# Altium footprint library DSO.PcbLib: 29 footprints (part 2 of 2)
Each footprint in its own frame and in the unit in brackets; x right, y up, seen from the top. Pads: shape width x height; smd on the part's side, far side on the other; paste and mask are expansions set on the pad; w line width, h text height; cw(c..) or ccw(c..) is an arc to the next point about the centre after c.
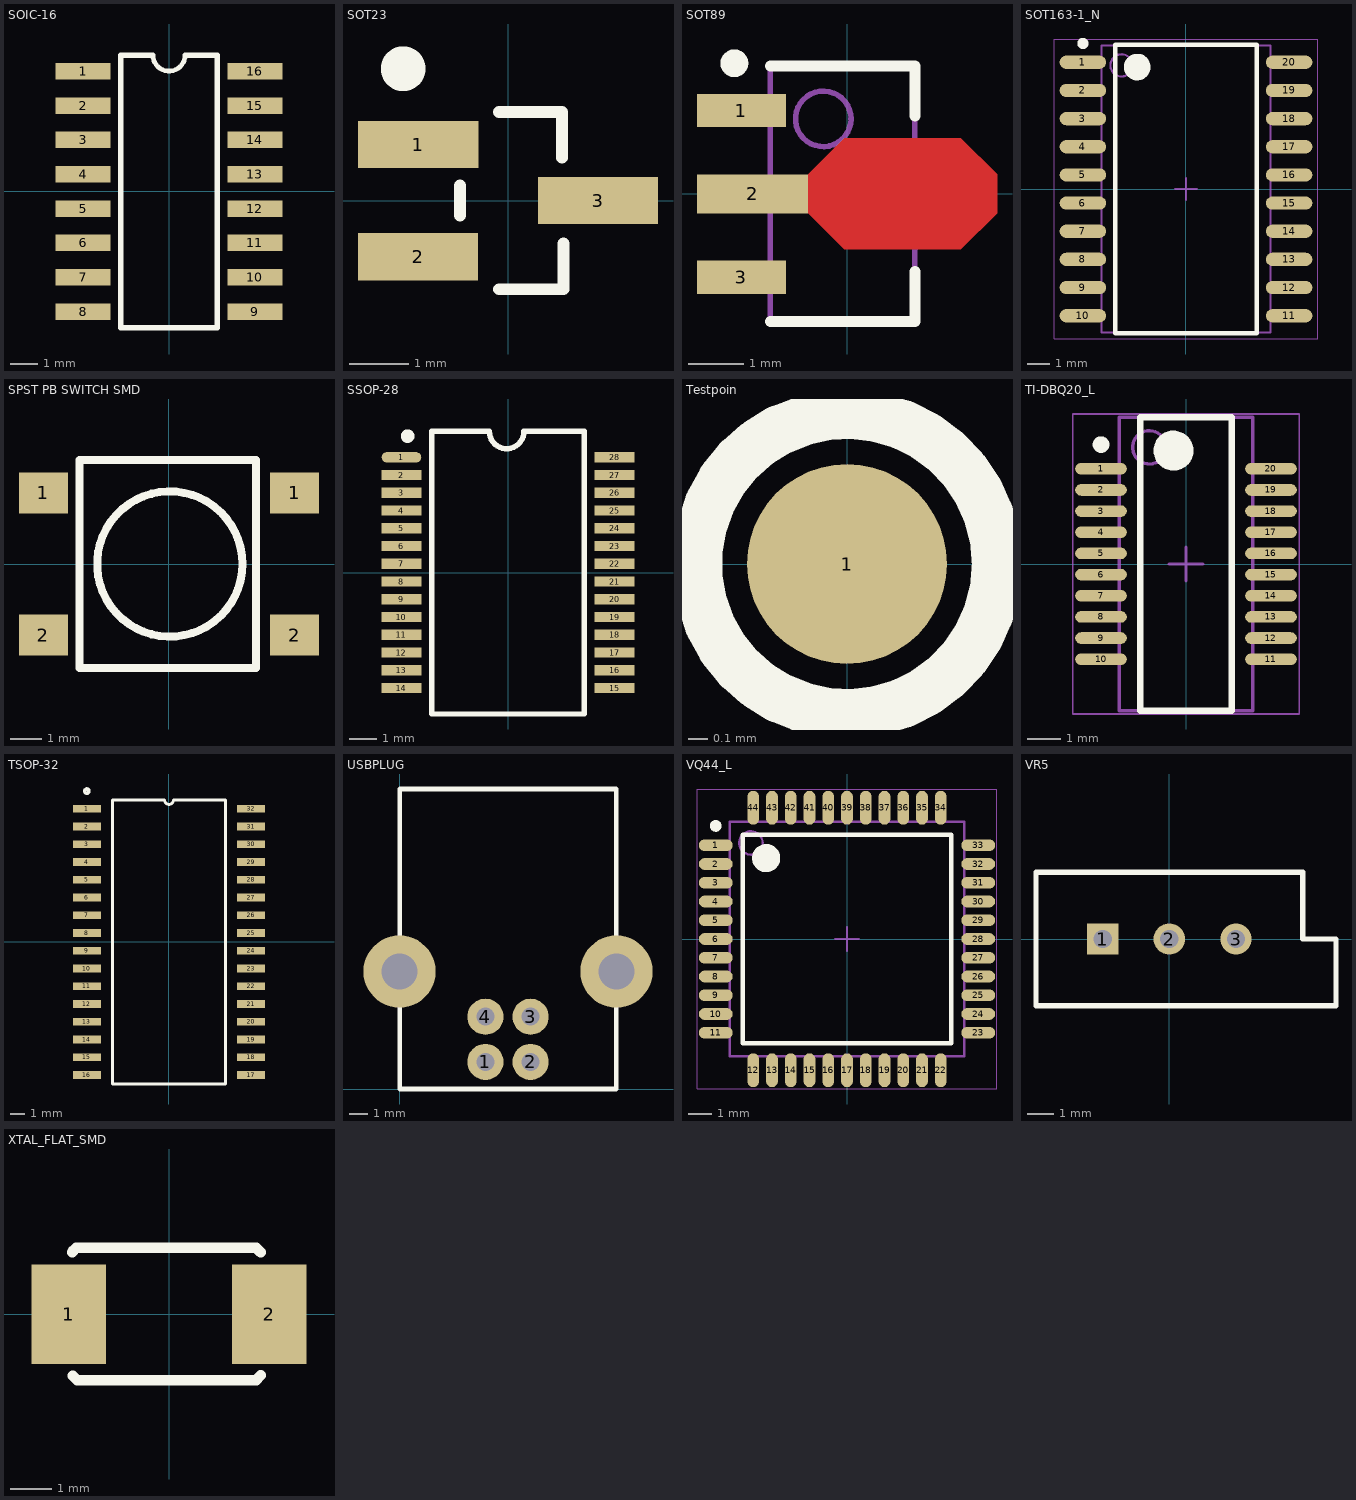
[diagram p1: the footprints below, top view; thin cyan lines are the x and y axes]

## SOIC-16 [mil] "SOIC-16 Footprint"
height 68.9
pads (16):
  rect 80x24 smd: 1(-125,175) 2(-125,125) 3(-125,75) 4(-125,25) 5(-125,-25) 6(-125,-75) 7(-125,-125) 8(-125,-175) 9(125,-175) 10(125,-125) 11(125,-75) 12(125,-25) 13(125,25) 14(125,75) 15(125,125) 16(125,175)
Top Overlay:
  lines w7: -23.43,198.43 ccw(c0,198.43) 23.43,198.43
  lines w7.87: -23.43,198.43 -70,198.43 -70,-198.43 70,-198.43 70,198.43 23.43,198.43
3D body "SOIC127P600X175-16M.step": height 68.9, standoff 0, extent -118.11,-196.85 118.11,196.85

## SOT23 [mm] "SOT23, 3-Leads, Body 3.0x2.5mm (max), Pitch 0.95mm, IPC Low Density"
height 1.35
pads (3):
  rect 2.038x0.8 smd: 1(-1.524,0.95)
  rect 2.032x0.8 smd: 2(-1.524,-0.95) 3(1.524,0)
Top Overlay:
  circle w0.508: c-1.776,2.235 r0.125
  lines w0.2: -0.813,-0.254 -0.813,0.254 ; -0.152,-1.5 0.94,-1.5 0.94,-0.725 ; -0.152,1.5 0.914,1.5 0.914,0.725
3D body "User Library-SOT23-2.step": height 1.08, standoff 0, extent -1.32,-1.5 1.32,1.5

## SOT89 [mm] "SOT89, 3-Leads, Body 4.50x2.50mm, Pitch 1.50mm, Lead Span 4.1mm, IPC Low Density"
height 1.6
pads (3):
  rect 1.6x0.6 smd: 1(-1.9,1.5) 3(-1.9,-1.5)
  rect 2x0.7 smd: 2(-1.7,0)
Top Layer:
  region: -0.7,0.35 -0.05,1 2.05,1 2.7,0.35 2.7,-0.35 2.05,-1 -0.05,-1 -0.7,-0.35
Top Overlay:
  circle w0.25: c-2.027,2.35 r0.125
  lines w0.2: -1.378,-2.3 1.222,-2.3 1.222,-1.4 ; -1.378,2.3 1.222,2.3 1.222,1.4
Mechanical 13:
  circle w0.1: c-0.427,1.35 r0.5
  lines w0.1: -1.378,-2.3 -1.378,2.3 1.222,2.3 1.222,-2.3 -1.378,-2.3
Mechanical 15:
  lines w0.1: -0.577,0 0.423,0 ; -0.078,-0.5 -0.078,0.5
3D body "SOT89-150P410X160-3M.step": height 1.6, standoff 0, extent -2.2,-2.3 1.85,2.3

## SOT163-1_N [mm] "SOIC, 20-Leads, Body 12.7x7.5mm, Pitch 1.27mm, IPC Medium Density"
height 2.54
pads (20):
  oval 2.1x0.6 smd: 1(-4.65,5.715) 2(-4.65,4.445) 3(-4.65,3.175) 4(-4.65,1.905) 5(-4.65,0.635) 6(-4.65,-0.635) 7(-4.65,-1.905) 8(-4.65,-3.175) 9(-4.65,-4.445) 10(-4.65,-5.715) 11(4.65,-5.715) 12(4.65,-4.445) 13(4.65,-3.175) 14(4.65,-1.905) 15(4.65,-0.635) 16(4.65,0.635) 17(4.65,1.905) 18(4.65,3.175) 19(4.65,4.445) 20(4.65,5.715)
Top Overlay:
  circle w0.6: c-2.2,5.5 r0.3
  circle w0.25: c-4.65,6.565 r0.125
  lines w0.2: -3.2,-6.5 3.2,-6.5 3.2,6.5 -3.2,6.5 -3.2,-6.5
Mechanical 13:
  circle w0.1: c-2.91,5.575 r0.5
  lines w0.1: -3.81,-6.475 3.81,-6.475 3.81,6.475 -3.81,6.475 -3.81,-6.475
Mechanical 15:
  lines w0.05: -5.95,-6.75 5.95,-6.75 5.95,6.75 -5.95,6.75 -5.95,-6.75
  lines w0.1: -0.5,0 0.5,0 ; 0,-0.5 0,0.5
3D body "SOIC127P1030X265-20M.step": height 2.65, standoff 0, extent -5.15,-6.5 5.15,6.5

## SPST PB SWITCH SMD [mm] "Push Button Switch Surface Mount"
height 3
pads (4):
  rect 1.55x1.3 smd: 1(-3.975,2.25) 1(3.975,2.25) 2(-3.975,-2.25) 2(3.975,-2.25)
Top Overlay:
  circle w0.254: c0.025,0 r2.3
  lines w0.254: -2.832,-3.3 2.756,-3.3 2.756,3.3 -2.832,3.3 -2.832,-3.3
3D body "PTS645SH50SMTR92LFS.stp": height 5, standoff 0, extent -4.5,-3 4.5,3

## SSOP-28 [mm] "Line Driver"
height 2
pads (28):
  oval 1.45x0.38 smd: 1(-3.9,4.225)
  rect 1.45x0.38 smd: 2(-3.9,3.575) 3(-3.9,2.925) 4(-3.9,2.275) 5(-3.9,1.625) 6(-3.9,0.975) 7(-3.9,0.325) 8(-3.9,-0.325) 9(-3.9,-0.975) 10(-3.9,-1.625) 11(-3.9,-2.275) 12(-3.9,-2.925) 13(-3.9,-3.575) 14(-3.9,-4.225) 15(3.9,-4.225) 16(3.9,-3.575) 17(3.9,-2.925) 18(3.9,-2.275) 19(3.9,-1.625) 20(3.9,-0.975) 21(3.9,-0.325) 22(3.9,0.325) 23(3.9,0.975) 24(3.9,1.625) 25(3.9,2.275) 26(3.9,2.925) 27(3.9,3.575) 28(3.9,4.225)
Top Overlay:
  circle w0.25: c-3.675,5 r0.125
  lines w0.2: -2.794,-5.175 -2.794,5.175 -0.685,5.175 ccw(c-0.05,5.175) 0.585,5.175 2.794,5.175 2.794,-5.175 -2.794,-5.175
3D body "TSSOP-28.STEP": height 2, standoff 0, extent -3.9,-5.1 3.9,5.1

## Testpoin [mil] "Testpoint"
pads (1):
  round 40 smd: 1(0,0)
Top Overlay:
  circle w10: c0,0 r30

## TI-DBQ20_L [mm] "SOP, 20-Leads, Body 8.65x3.9mm, Pitch 0.635mm, IPC High Density"
height 1.75
pads (20):
  oval 1.55x0.35 smd: 1(-2.55,2.857) 2(-2.55,2.222) 3(-2.55,1.587) 4(-2.55,0.953) 5(-2.55,0.318) 6(-2.55,-0.318) 7(-2.55,-0.953) 8(-2.55,-1.587) 9(-2.55,-2.222) 10(-2.55,-2.857) 11(2.55,-2.857) 12(2.55,-2.222) 13(2.55,-1.587) 14(2.55,-0.953) 15(2.55,-0.318) 16(2.55,0.318) 17(2.55,0.953) 18(2.55,1.587) 19(2.55,2.222) 20(2.55,2.857)
Top Overlay:
  circle w0.25: c-2.55,3.582 r0.125
  circle w0.6: c-0.375,3.4 r0.3
  lines w0.2: -1.375,-4.4 -1.375,4.4 1.375,4.4 1.375,-4.4 -1.375,-4.4
Mechanical 13:
  circle w0.1: c-1.1,3.5 r0.5
  lines w0.1: -2,-4.4 -2,4.4 2,4.4 2,-4.4 -2,-4.4
Mechanical 15:
  lines w0.05: -3.4,-4.5 -3.4,4.5 3.4,4.5 3.4,-4.5 -3.4,-4.5
  lines w0.1: -0.5,0 0.5,0 ; 0,-0.5 0,0.5
3D body "SOP64P600X175-20N.step": height 1.75, standoff 0, extent -3,-4.4 3,4.4

## TSOP-32 [mm]
height 5
pads (32):
  rect 2x0.55 smd: 1(-5.88,9.525) 2(-5.88,8.255) 3(-5.88,6.985) 4(-5.88,5.715) 5(-5.88,4.445) 6(-5.88,3.175) 7(-5.88,1.905) 8(-5.88,0.635) 9(-5.88,-0.635) 10(-5.88,-1.905) 11(-5.88,-3.175) 12(-5.88,-4.445) 13(-5.88,-5.715) 14(-5.88,-6.985) 15(-5.88,-8.255) 16(-5.88,-9.525) 17(5.88,-9.525) 18(5.88,-8.255) 19(5.88,-6.985) 20(5.88,-5.715) 21(5.88,-4.445) 22(5.88,-3.175) 23(5.88,-1.905) 24(5.88,-0.635) 25(5.88,0.635) 26(5.88,1.905) 27(5.88,3.175) 28(5.88,4.445) 29(5.88,5.715) 30(5.88,6.985) 31(5.88,8.255) 32(5.88,9.525)
Top Overlay:
  circle w0.254: c-5.88,10.795 r0.15
  lines w0.2: -4.045,-10.16 -4.045,10.16 -0.318,10.16 ccw(c0,10.16) 0.318,10.16 4.045,10.16 4.045,-10.16 -4.045,-10.16
3D body "TSOP127P1180X120-32N.step": height 1.2, standoff 0, extent -5.88,-10.55 5.88,10.55

## USBPLUG [mm]
height 1.3
pads (6):
  round 2 hole 1: 1(4.75,1.5) 2(7.25,1.5) 3(7.25,4) 4(4.75,4)
  round 4 hole 2: ""(0,6.5) ""(12,6.5)
Top Overlay:
  lines w0.254: 11.9,0 0,0 0,16.6 12,16.6 12,0
3D body "Download_STP_61400416121 (rev1).stp": height 11.06, standoff -3.79, extent -1.515,0.292 13.453,16.792

## VQ44_L [mm] "Thin QFP, 44-Leads, Body 10x10mm, Pitch 0.8mm, IPC High Density"
height 1.2
pads (44):
  oval 1.45x0.5 smd: 1(-5.6,4) 2(-5.6,3.2) 3(-5.6,2.4) 4(-5.6,1.6) 5(-5.6,0.8) 6(-5.6,0) 7(-5.6,-0.8) 8(-5.6,-1.6) 9(-5.6,-2.4) 10(-5.6,-3.2) 11(-5.6,-4) 23(5.6,-4) 24(5.6,-3.2) 25(5.6,-2.4) 26(5.6,-1.6) 27(5.6,-0.8) 28(5.6,0) 29(5.6,0.8) 30(5.6,1.6) 31(5.6,2.4) 32(5.6,3.2) 33(5.6,4)
  oval 0.5x1.45 smd: 12(-4,-5.6) 13(-3.2,-5.6) 14(-2.4,-5.6) 15(-1.6,-5.6) 16(-0.8,-5.6) 17(0,-5.6) 18(0.8,-5.6) 19(1.6,-5.6) 20(2.4,-5.6) 21(3.2,-5.6) 22(4,-5.6) 34(4,5.6) 35(3.2,5.6) 36(2.4,5.6) 37(1.6,5.6) 38(0.8,5.6) 39(0,5.6) 40(-0.8,5.6) 41(-1.6,5.6) 42(-2.4,5.6) 43(-3.2,5.6) 44(-4,5.6)
Top Overlay:
  circle w0.6: c-3.45,3.45 r0.3
  circle w0.25: c-5.6,4.825 r0.125
  lines w0.2: -4.45,-4.45 4.45,-4.45 4.45,4.45 -4.45,4.45 -4.45,-4.45
Mechanical 13:
  circle w0.1: c-4.1,4.1 r0.5
  lines w0.1: -5,-5 5,-5 5,5 -5,5 -5,-5
Mechanical 15:
  lines w0.05: -6.4,-6.4 6.4,-6.4 6.4,6.4 -6.4,6.4 -6.4,-6.4
  lines w0.1: -0.5,0 0.5,0 ; 0,-0.5 0,0.5
3D body "User Library-44 pin tqfp ic package.step": height 1.13, standoff 0.02, extent -5.974,-6 6.026,6

## VR5 [mm] "Thru-Hole; 3 Leads"
pads (3):
  rect 1.2x1.2 hole 0.7: 1(-2.54,0)
  round 1.2 hole 0.7: 2(0,0) 3(2.54,0)
Top Overlay:
  lines w0.2: -5.08,-2.54 6.35,-2.54 6.35,0 5.08,0 5.08,2.54 -5.08,2.54 -5.08,-2.54

## XTAL_FLAT_SMD [mm]
height 1.35
pads (2):
  rect 1.8x2.4 smd: 1(-2.412,0) 2(2.412,0)
Top Overlay:
  lines w0.254: -2.335,1.498 -2.232,1.6 2.096,1.6 2.204,1.492 ; -2.319,-1.481 -2.211,-1.589 2.096,-1.589 2.212,-1.474
3D body "CRYSTAL_TXC_7A.stp": height 1.35, standoff 0, extent -2.578,-1.676 2.578,1.676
